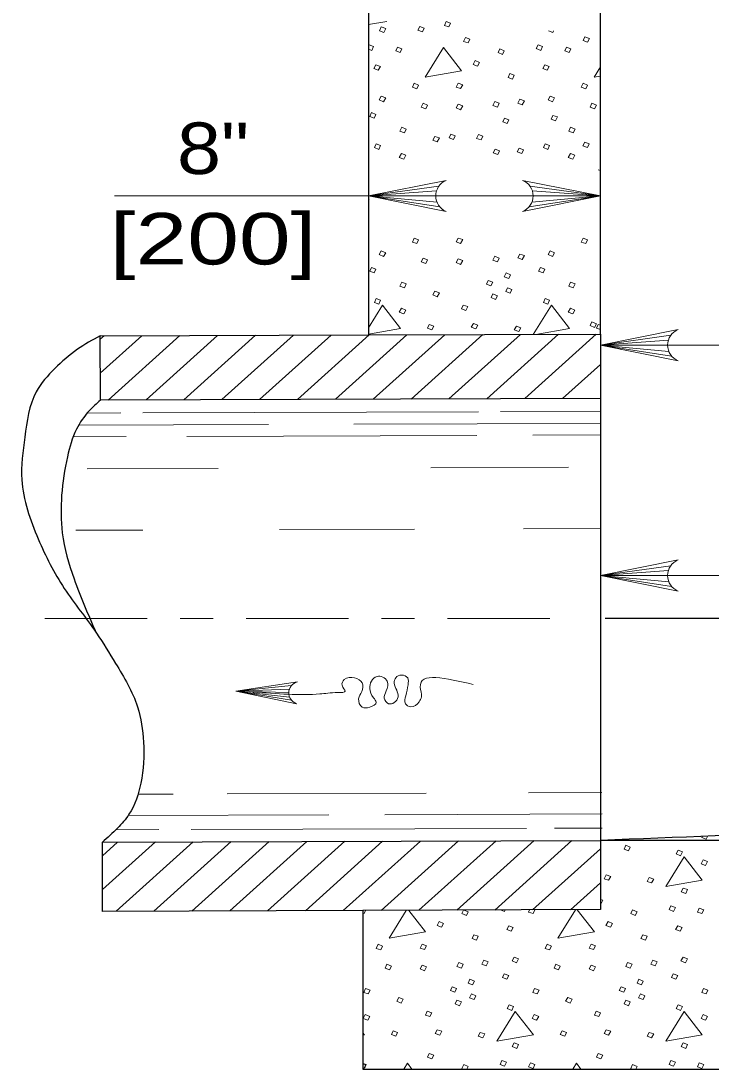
# Model space of a CAD drawing. Extents: x 1083.1 to 1123, y 697.4 to 741.4.
# Drawn here: x 1086.984 to 1089.075, y 699.494 to 702.669 of the extents above; entities that cross this region are included whole.
import ezdxf
from ezdxf.enums import TextEntityAlignment as Align

# ---------------------------------------------------------------- set-up
doc = ezdxf.new("R2010")
doc.units = 0
doc.header["$LTSCALE"] = 0.062
doc.linetypes.add('DOT_DASHED', pattern=[7.7, 5, -1.2, 0.3, -1.2])
doc.layers.add('1', color=7, linetype='Continuous', lineweight=13)

msp = doc.modelspace()

# ---------------------------------------------------------------- linework, layer by layer
at = {"layer": '1', "lineweight": 25}
for p, q in [((1088.03742, 703.9655), (1088.03742, 701.71783)), ((1088.74, 701.72025), (1088.74, 703.03767)), ((1088.74, 701.72025), (1088.74, 700.18692)), ((1095.16083, 700.18692), (1088.74, 700.18692))]:
    msp.add_line(p, q, dxfattribs=at)
at = {"layer": '1'}
for p, q in [((1088.03742, 702.65775), (1088.09258, 702.66742)), ((1088.03742, 702.59242), (1088.03933, 702.59642)), ((1088.73342, 702.21817), (1088.74, 702.21583)), ((1088.25067, 702.16858), (1088.03742, 702.13875)), ((1088.2435, 702.15383), (1088.03742, 702.13875)), ((1088.52675, 702.16858), (1088.74, 702.13875)), ((1088.53392, 702.15383), (1088.74, 702.13875)), ((1088.74, 702.13875), (1087.26767, 702.13875)), ((1088.24125, 702.13875), (1088.03742, 702.13875)), ((1088.24508, 702.11958), (1088.03742, 702.13875)), ((1088.25325, 702.10575), (1088.03742, 702.13875)), ((1088.03742, 702.12375), (1088.03933, 702.12767)), ((1088.52425, 702.10575), (1088.74, 702.13875)), ((1088.53242, 702.11958), (1088.74, 702.13875)), ((1088.53617, 702.13875), (1088.74, 702.13875)), ((1088.07975, 701.80767), (1088.03742, 701.73958)), ((1088.59158, 701.80767), (1088.53692, 701.7195)), ((1088.73342, 701.7495), (1088.74, 701.74717)), ((1087.2245, 701.70458), (1087.23633, 701.71508)), ((1087.225, 701.60208), (1087.351, 701.7155)), ((1087.24883, 701.52067), (1087.46575, 701.71592)), ((1087.36358, 701.521), (1087.5805, 701.71625)), ((1087.47825, 701.52142), (1087.69517, 701.71667)), ((1087.593, 701.52183), (1087.80992, 701.717)), ((1087.70767, 701.52217), (1087.92467, 701.71742)), ((1087.82242, 701.52258), (1088.03942, 701.71783)), ((1087.93717, 701.523), (1088.15417, 701.71825)), ((1088.05192, 701.52342), (1088.26883, 701.71858)), ((1088.16667, 701.52375), (1088.38358, 701.719)), ((1088.28142, 701.52417), (1088.49833, 701.71942)), ((1088.39608, 701.5245), (1088.613, 701.71983)), ((1088.51083, 701.52492), (1088.72783, 701.72017)), ((1088.541, 701.71958), (1088.54108, 701.71958)), ((1088.54108, 701.71958), (1088.54117, 701.71958)), ((1088.54117, 701.71958), (1088.54125, 701.71958)), ((1088.54125, 701.71958), (1088.54142, 701.71958)), ((1088.54142, 701.71958), (1088.54158, 701.71958)), ((1088.54158, 701.71958), (1088.54175, 701.71958)), ((1088.54175, 701.71958), (1088.54192, 701.71958)), ((1088.54192, 701.71958), (1088.54208, 701.71958)), ((1088.54208, 701.71958), (1088.54225, 701.71958)), ((1088.54225, 701.71958), (1088.54242, 701.71958)), ((1088.54242, 701.71958), (1088.54267, 701.71958)), ((1088.54267, 701.71958), (1088.54283, 701.71958)), ((1088.54283, 701.71958), (1088.543, 701.71958)), ((1088.543, 701.71958), (1088.54317, 701.71958)), ((1088.54317, 701.71958), (1088.54333, 701.71958)), ((1088.54333, 701.71958), (1088.5435, 701.71958)), ((1088.5435, 701.71958), (1088.54375, 701.71958)), ((1088.54375, 701.71958), (1088.54392, 701.71958)), ((1088.54392, 701.71958), (1088.54408, 701.71958)), ((1088.54408, 701.71958), (1088.54425, 701.71958)), ((1088.54425, 701.71958), (1088.54442, 701.71958)), ((1088.54442, 701.71958), (1088.54458, 701.71958)), ((1088.54458, 701.71958), (1088.54483, 701.71958)), ((1088.54483, 701.71958), (1088.545, 701.71958)), ((1088.95333, 701.71675), (1088.74, 701.68692)), ((1088.94608, 701.702), (1088.74, 701.68692)), ((1090.56375, 701.68692), (1088.74, 701.68692)), ((1088.94392, 701.68692), (1088.74, 701.68692)), ((1088.94767, 701.66775), (1088.74, 701.68692)), ((1088.95583, 701.65392), (1088.74, 701.68692)), ((1088.62558, 701.52533), (1088.74, 701.62833)), ((1087.28708, 701.48167), (1087.18492, 701.48133)), ((1088.37108, 701.48542), (1087.35375, 701.48192)), ((1088.74008, 701.48667), (1088.43775, 701.48567)), ((1087.73458, 701.4465), (1087.15925, 701.44458)), ((1088.74017, 701.45), (1087.993, 701.44742)), ((1087.30375, 701.41), (1087.14358, 701.40942)), ((1088.36542, 701.41367), (1087.48725, 701.41067)), ((1088.74042, 701.41492), (1088.53508, 701.41425)), ((1088.64342, 701.317), (1088.22642, 701.3155)), ((1087.58167, 701.31333), (1087.18558, 701.312)), ((1087.35367, 701.12683), (1087.15083, 701.12617)), ((1088.1765, 701.12967), (1087.76792, 701.12833)), ((1088.7415, 701.13158), (1088.50725, 701.13083)), ((1088.95333, 701.019), (1088.74, 700.98917)), ((1088.94608, 701.00425), (1088.74, 700.98917)), ((1094.45983, 700.98917), (1088.74, 700.98917)), ((1088.94392, 700.98917), (1088.74, 700.98917)), ((1088.94767, 700.97), (1088.74, 700.98917)), ((1088.95583, 700.95617), (1088.74, 700.98917)), ((1087.80417, 700.65567), (1087.63575, 700.63925)), ((1087.798, 700.64533), (1087.63575, 700.63925)), ((1087.796, 700.63475), (1087.63575, 700.63925)), ((1087.7985, 700.62108), (1087.63575, 700.63925)), ((1087.8045, 700.61117), (1087.63575, 700.63925)), ((1088.74492, 700.332), (1088.52233, 700.33117)), ((1087.44533, 700.32742), (1087.33933, 700.32717)), ((1088.21208, 700.33008), (1087.60958, 700.328)), ((1087.91692, 700.26408), (1087.30883, 700.262)), ((1088.74525, 700.26692), (1088.08725, 700.26467)), ((1087.40267, 700.21967), (1087.27175, 700.21917)), ((1088.51625, 700.22342), (1087.50008, 700.22)), ((1088.74542, 700.22425), (1088.60133, 700.22375)), ((1087.23125, 700.1405), (1087.27725, 700.18192)), ((1087.23167, 700.038), (1087.392, 700.18233)), ((1087.27267, 699.97217), (1087.50667, 700.18275)), ((1087.38742, 699.9725), (1087.6215, 700.18308)), ((1087.50225, 699.97283), (1087.73625, 700.18342)), ((1087.61692, 699.97325), (1087.85092, 700.18383)), ((1087.73167, 699.97367), (1087.96567, 700.18425)), ((1087.84633, 699.97408), (1088.08042, 700.18467)), ((1087.96108, 699.9745), (1088.19508, 700.18508)), ((1088.07583, 699.97475), (1088.30992, 700.1855)), ((1088.1905, 699.97517), (1088.42467, 700.18583)), ((1088.30533, 699.97558), (1088.53933, 700.18617)), ((1088.42008, 699.976), (1088.65408, 700.18658)), ((1088.53483, 699.97642), (1088.74, 700.16117)), ((1088.6495, 699.97683), (1088.74, 700.05825)), ((1088.15542, 699.51175), (1088.14467, 699.49442)), ((1088.16892, 699.49442), (1088.15542, 699.51175)), ((1088.66725, 699.51175), (1088.6565, 699.49442)), ((1088.68075, 699.49442), (1088.66725, 699.51175))]:
    msp.add_line(p, q, dxfattribs=at)
at = {"layer": '1', "linetype": 'DOT_DASHED'}
msp.add_line((1088.58675, 700.85858), (1086.9945, 700.85858), dxfattribs=at)
at = {"layer": '1'}
for points in [[(1088.07617, 702.65058), (1088.08958, 702.64567), (1088.08417, 702.63358), (1088.07075, 702.63925)], [(1088.19258, 702.65225), (1088.206, 702.64742), (1088.20067, 702.63608), (1088.18717, 702.64092)], [(1088.27283, 702.66683), (1088.28625, 702.662), (1088.28092, 702.65067), (1088.26742, 702.6555)], [(1088.33117, 702.61825), (1088.34458, 702.61333), (1088.33925, 702.60208), (1088.32575, 702.60692)], [(1088.6935, 702.62067), (1088.70692, 702.61583), (1088.70158, 702.6045), (1088.68808, 702.60933)], [(1088.1255, 702.58992), (1088.139, 702.58425), (1088.13358, 702.573), (1088.12008, 702.57783)], [(1088.26467, 702.58833), (1088.209, 702.49858), (1088.3195, 702.518)], [(1088.55117, 702.59642), (1088.56467, 702.59158), (1088.55925, 702.57942), (1088.54575, 702.58508)], [(1088.63742, 702.58992), (1088.65083, 702.58425), (1088.64542, 702.573), (1088.632, 702.57783)], [(1088.43533, 702.58425), (1088.44883, 702.57858), (1088.44342, 702.56733), (1088.42992, 702.573)], [(1088.06, 702.53583), (1088.07342, 702.53092), (1088.06717, 702.51967), (1088.05367, 702.5245)], [(1088.36075, 702.54875), (1088.37425, 702.54308), (1088.368, 702.53175), (1088.3545, 702.53658)], [(1088.57183, 702.53583), (1088.58533, 702.53092), (1088.579, 702.51967), (1088.5655, 702.5245)], [(1088.46583, 702.50917), (1088.47933, 702.50425), (1088.47392, 702.49217), (1088.4605, 702.49783)], [(1088.17583, 702.48), (1088.18925, 702.47442), (1088.18392, 702.46308), (1088.17042, 702.46792)], [(1088.30958, 702.48), (1088.32308, 702.47517), (1088.31675, 702.46383), (1088.30333, 702.46875)], [(1088.68767, 702.48), (1088.70117, 702.47442), (1088.69575, 702.46308), (1088.68225, 702.46792)], [(1088.07617, 702.44125), (1088.08958, 702.43558), (1088.08333, 702.42425), (1088.06983, 702.42992)], [(1088.49642, 702.43158), (1088.50983, 702.42667), (1088.50358, 702.41458), (1088.49008, 702.42025)], [(1088.588, 702.44125), (1088.60142, 702.43558), (1088.59517, 702.42425), (1088.58167, 702.42992)], [(1088.20275, 702.41942), (1088.21617, 702.41375), (1088.21083, 702.40242), (1088.19733, 702.40808)], [(1088.30958, 702.417), (1088.32308, 702.41217), (1088.31675, 702.4), (1088.30333, 702.40567)], [(1088.42008, 702.42508), (1088.4335, 702.41942), (1088.42817, 702.40808), (1088.41467, 702.413)], [(1088.71458, 702.41942), (1088.72808, 702.41375), (1088.72267, 702.40242), (1088.70925, 702.40808)], [(1088.0465, 702.39117), (1088.06, 702.3855), (1088.05458, 702.37417), (1088.04108, 702.37983)], [(1088.44958, 702.37433), (1088.463, 702.3695), (1088.45767, 702.35817), (1088.44417, 702.363)], [(1088.59633, 702.38283), (1088.60983, 702.378), (1088.60442, 702.36667), (1088.59092, 702.3715)], [(1088.13808, 702.34667), (1088.15158, 702.341), (1088.14617, 702.32975), (1088.13267, 702.33458)], [(1088.64992, 702.34667), (1088.66342, 702.341), (1088.658, 702.32975), (1088.64458, 702.33458)], [(1088.23867, 702.31925), (1088.25217, 702.31433), (1088.24583, 702.30225), (1088.23242, 702.30792)], [(1088.28692, 702.32592), (1088.30042, 702.32108), (1088.295, 702.30975), (1088.28158, 702.31467)], [(1088.37058, 702.3245), (1088.38408, 702.31967), (1088.37867, 702.30833), (1088.36525, 702.31325)], [(1088.69267, 702.30175), (1088.70608, 702.29692), (1088.70075, 702.28558), (1088.68725, 702.29042)], [(1088.06083, 702.29658), (1088.07433, 702.29175), (1088.06892, 702.27967), (1088.0555, 702.28525)], [(1088.13717, 702.2675), (1088.15067, 702.26183), (1088.14433, 702.2505), (1088.13092, 702.25533)], [(1088.42117, 702.28042), (1088.43458, 702.27558), (1088.42925, 702.26425), (1088.41575, 702.26908)], [(1088.49375, 702.28325), (1088.50725, 702.27842), (1088.50183, 702.26708), (1088.48833, 702.27192)], [(1088.57275, 702.29658), (1088.58617, 702.29175), (1088.58083, 702.27967), (1088.56733, 702.28525)], [(1088.64908, 702.2675), (1088.6625, 702.26183), (1088.65625, 702.2505), (1088.64275, 702.25533)], [(1088.17583, 702.01133), (1088.18925, 702.00567), (1088.18392, 701.99433), (1088.17042, 701.99917)], [(1088.30958, 702.01133), (1088.32308, 702.0065), (1088.31675, 701.99517), (1088.30333, 702)], [(1088.68767, 702.01133), (1088.70117, 702.00567), (1088.69575, 701.99433), (1088.68225, 701.99917)], [(1088.07617, 701.9725), (1088.08958, 701.96683), (1088.08333, 701.95558), (1088.06983, 701.96125)], [(1088.20275, 701.95075), (1088.21617, 701.94508), (1088.21083, 701.93375), (1088.19733, 701.93942)], [(1088.42008, 701.95642), (1088.4335, 701.95075), (1088.42817, 701.93942), (1088.41467, 701.94425)], [(1088.49642, 701.96283), (1088.50983, 701.958), (1088.50358, 701.94583), (1088.49008, 701.9515)], [(1088.588, 701.9725), (1088.60142, 701.96683), (1088.59517, 701.95558), (1088.58167, 701.96125)], [(1088.0465, 701.92242), (1088.06, 701.91675), (1088.05458, 701.9055), (1088.04108, 701.91108)], [(1088.30958, 701.94825), (1088.32308, 701.94342), (1088.31675, 701.93133), (1088.30333, 701.937)], [(1088.55833, 701.92242), (1088.57183, 701.91675), (1088.56642, 701.9055), (1088.553, 701.91108)], [(1088.45417, 701.9055), (1088.46767, 701.89983), (1088.46225, 701.8885), (1088.44883, 701.89333)], [(1088.13808, 701.878), (1088.15158, 701.87233), (1088.14617, 701.861), (1088.13267, 701.86583)], [(1088.40033, 701.88283), (1088.41375, 701.878), (1088.40842, 701.86667), (1088.39492, 701.8715)], [(1088.45867, 701.861), (1088.47217, 701.85533), (1088.46675, 701.84408), (1088.45325, 701.84967)], [(1088.64992, 701.878), (1088.66342, 701.87233), (1088.658, 701.861), (1088.64458, 701.86583)], [(1088.06083, 701.82792), (1088.07433, 701.823), (1088.06892, 701.81092), (1088.0555, 701.81658)], [(1088.23867, 701.8505), (1088.25217, 701.84567), (1088.24583, 701.8335), (1088.23242, 701.83917)], [(1088.41467, 701.84242), (1088.42817, 701.83675), (1088.42275, 701.8255), (1088.40925, 701.83108)], [(1088.57275, 701.82792), (1088.58617, 701.823), (1088.58083, 701.81092), (1088.56733, 701.81658)], [(1088.13717, 701.79883), (1088.15067, 701.79317), (1088.14433, 701.78183), (1088.13092, 701.78667)], [(1088.32483, 701.8085), (1088.33833, 701.80367), (1088.33292, 701.79233), (1088.3195, 701.79717)], [(1088.64908, 701.79883), (1088.6625, 701.79317), (1088.65625, 701.78183), (1088.64275, 701.78667)], [(1088.22158, 701.7495), (1088.23508, 701.74467), (1088.22967, 701.73333), (1088.21617, 701.73817)], [(1088.35542, 701.75275), (1088.36883, 701.74792), (1088.36258, 701.73658), (1088.34908, 701.74142)], [(1088.48558, 701.74467), (1088.49908, 701.73983), (1088.49283, 701.7285), (1088.47933, 701.73333)], [(1088.71458, 701.75742), (1088.72808, 701.75175), (1088.72267, 701.74042), (1088.70925, 701.74608)], [(1088.81725, 700.172), (1088.83075, 700.16633), (1088.82533, 700.155), (1088.81183, 700.16067)], [(1088.97533, 700.15742), (1088.98875, 700.15258), (1088.98333, 700.14042), (1088.96992, 700.14608)], [(1088.99417, 700.13725), (1088.9385, 700.0475), (1089.04892, 700.06692)], [(1089.05158, 700.12833), (1089.06508, 700.12267), (1089.05883, 700.11133), (1089.04533, 700.11625)], [(1088.758, 700.08225), (1088.77142, 700.07742), (1088.76517, 700.06608), (1088.75167, 700.07092)], [(1088.88817, 700.07417), (1088.90167, 700.06933), (1088.89533, 700.058), (1088.88192, 700.06283)], [(1088.99058, 700.04267), (1089.004, 700.03783), (1088.99867, 700.02567), (1088.98517, 700.03133)], [(1088.95375, 699.9885), (1088.96725, 699.98367), (1088.96183, 699.97158), (1088.94833, 699.97725)], [(1089.03992, 699.98208), (1089.05342, 699.97642), (1089.048, 699.96508), (1089.03458, 699.96992)], [(1088.83792, 699.97642), (1088.85133, 699.97075), (1088.846, 699.95942), (1088.8325, 699.96508)], [(1088.2515, 699.94083), (1088.265, 699.93517), (1088.25867, 699.92383), (1088.24525, 699.92875)], [(1088.4625, 699.92792), (1088.476, 699.92308), (1088.46975, 699.91175), (1088.45625, 699.91658)], [(1088.76333, 699.94083), (1088.77683, 699.93517), (1088.77058, 699.92383), (1088.75708, 699.92875)], [(1088.97442, 699.92792), (1088.98783, 699.92308), (1088.98158, 699.91175), (1088.96808, 699.91658)], [(1088.35658, 699.90125), (1088.37, 699.89642), (1088.36467, 699.88425), (1088.35117, 699.88992)], [(1088.86842, 699.90125), (1088.88192, 699.89642), (1088.8765, 699.88425), (1088.86308, 699.88992)], [(1088.0665, 699.87217), (1088.08, 699.8665), (1088.07458, 699.85517), (1088.06108, 699.86)], [(1088.20033, 699.87217), (1088.21375, 699.86733), (1088.2075, 699.856), (1088.194, 699.86083)], [(1088.57842, 699.87217), (1088.59183, 699.8665), (1088.58642, 699.85517), (1088.573, 699.86)], [(1088.71217, 699.87217), (1088.72567, 699.86733), (1088.71933, 699.856), (1088.70592, 699.86083)], [(1088.38708, 699.82367), (1088.40058, 699.81883), (1088.39425, 699.80667), (1088.38083, 699.81233)], [(1088.47867, 699.83342), (1088.49217, 699.82775), (1088.48592, 699.81642), (1088.47242, 699.82208)], [(1088.899, 699.82367), (1088.91242, 699.81883), (1088.90617, 699.80667), (1088.89267, 699.81233)], [(1088.99058, 699.83342), (1089.004, 699.82775), (1088.99775, 699.81642), (1088.98425, 699.82208)], [(1088.09342, 699.81158), (1088.10692, 699.80592), (1088.10158, 699.79458), (1088.08808, 699.80025)], [(1088.20033, 699.80908), (1088.21375, 699.80425), (1088.2075, 699.79217), (1088.194, 699.79783)], [(1088.31075, 699.81725), (1088.32425, 699.81158), (1088.31883, 699.80025), (1088.30542, 699.80508)], [(1088.60533, 699.81158), (1088.61875, 699.80592), (1088.61342, 699.79458), (1088.59992, 699.80025)], [(1088.71217, 699.80908), (1088.72567, 699.80425), (1088.71933, 699.79217), (1088.70592, 699.79783)], [(1088.82267, 699.81725), (1088.83608, 699.81158), (1088.83075, 699.80025), (1088.81725, 699.80508)], [(1088.34492, 699.76625), (1088.35833, 699.76067), (1088.353, 699.74933), (1088.3395, 699.75417)], [(1088.44908, 699.78325), (1088.4625, 699.77758), (1088.45717, 699.76625), (1088.44367, 699.77192)], [(1088.85675, 699.76625), (1088.87025, 699.76067), (1088.86483, 699.74933), (1088.85133, 699.75417)], [(1088.96092, 699.78325), (1088.97442, 699.77758), (1088.969, 699.76625), (1088.9555, 699.77192)], [(1088.02883, 699.73883), (1088.04225, 699.73317), (1088.03692, 699.72183), (1088.02342, 699.72667)], [(1088.291, 699.74367), (1088.3045, 699.73883), (1088.29908, 699.7275), (1088.28567, 699.73233)], [(1088.54067, 699.73883), (1088.55417, 699.73317), (1088.54875, 699.72183), (1088.53525, 699.72667)], [(1088.80292, 699.74367), (1088.81633, 699.73883), (1088.811, 699.7275), (1088.7975, 699.73233)], [(1089.0525, 699.73883), (1089.066, 699.73317), (1089.06058, 699.72183), (1089.04717, 699.72667)], [(1088.12942, 699.71133), (1088.14283, 699.7065), (1088.13658, 699.69433), (1088.12308, 699.7)], [(1088.30542, 699.70325), (1088.31883, 699.69758), (1088.3135, 699.68625), (1088.3, 699.69192)], [(1088.34942, 699.72183), (1088.36283, 699.71617), (1088.3575, 699.70492), (1088.344, 699.7105)], [(1088.64125, 699.71133), (1088.65467, 699.7065), (1088.64842, 699.69433), (1088.63492, 699.7)], [(1088.81725, 699.70325), (1088.83075, 699.69758), (1088.82533, 699.68625), (1088.81183, 699.69192)], [(1088.86125, 699.72183), (1088.87475, 699.71617), (1088.86933, 699.70492), (1088.85583, 699.7105)], [(1088.21558, 699.66933), (1088.22908, 699.6645), (1088.22367, 699.65317), (1088.21017, 699.658)], [(1088.48233, 699.6685), (1088.42658, 699.57883), (1088.53708, 699.59825)], [(1088.46342, 699.68875), (1088.47692, 699.68383), (1088.4715, 699.67175), (1088.458, 699.67742)], [(1088.72742, 699.66933), (1088.74092, 699.6645), (1088.7355, 699.65317), (1088.72208, 699.658)], [(1088.99417, 699.6685), (1088.9385, 699.57883), (1089.04892, 699.59825)], [(1088.97533, 699.68875), (1088.98875, 699.68383), (1088.98333, 699.67175), (1088.96992, 699.67742)], [(1088.02792, 699.65967), (1088.04133, 699.654), (1088.03508, 699.64267), (1088.02158, 699.6475)], [(1088.53975, 699.65967), (1088.55325, 699.654), (1088.54692, 699.64267), (1088.5335, 699.6475)], [(1089.05158, 699.65967), (1089.06508, 699.654), (1089.05883, 699.64267), (1089.04533, 699.6475)], [(1088.11233, 699.61033), (1088.12575, 699.6055), (1088.12042, 699.59417), (1088.10692, 699.599)], [(1088.24608, 699.61358), (1088.25958, 699.60875), (1088.25333, 699.59742), (1088.23983, 699.60225)], [(1088.37633, 699.6055), (1088.38983, 699.60067), (1088.3835, 699.58933), (1088.37, 699.59417)], [(1088.62417, 699.61033), (1088.63767, 699.6055), (1088.63225, 699.59417), (1088.61875, 699.599)], [(1088.758, 699.61358), (1088.77142, 699.60875), (1088.76517, 699.59742), (1088.75167, 699.60225)], [(1088.88817, 699.6055), (1088.90167, 699.60067), (1088.89533, 699.58933), (1088.88192, 699.59417)], [(1088.47867, 699.574), (1088.49217, 699.56908), (1088.48675, 699.557), (1088.47333, 699.56267)], [(1088.99058, 699.574), (1089.004, 699.56908), (1088.99867, 699.557), (1088.98517, 699.56267)], [(1088.22183, 699.54167), (1088.23533, 699.53675), (1088.22992, 699.5255), (1088.2165, 699.53033)], [(1088.73375, 699.54167), (1088.74717, 699.53675), (1088.74183, 699.5255), (1088.72833, 699.53033)], [(1088.44192, 699.51983), (1088.45533, 699.515), (1088.44992, 699.50283), (1088.4365, 699.5085)], [(1088.52808, 699.51333), (1088.54158, 699.50767), (1088.53617, 699.49642), (1088.52267, 699.50125)], [(1088.95375, 699.51983), (1088.96725, 699.515), (1088.96183, 699.50283), (1088.94833, 699.5085)], [(1089.03992, 699.51333), (1089.05342, 699.50767), (1089.048, 699.49642), (1089.03458, 699.50125)]]:
    msp.add_lwpolyline(points, close=True, dxfattribs=at)
for points in [[(1088.5985, 702.639), (1088.59608, 702.63358), (1088.58308, 702.639)], [(1088.03933, 702.59642), (1088.05275, 702.59158), (1088.04742, 702.57942), (1088.03742, 702.58367)], [(1088.74, 702.52942), (1088.72092, 702.49858), (1088.74, 702.502)], [(1088.273, 702.09167), (1088.03742, 702.13875), (1088.273, 702.18592)], [(1088.50442, 702.09167), (1088.74, 702.13875), (1088.50442, 702.18592)], [(1088.03742, 701.72033), (1088.1345, 701.73733), (1088.07975, 701.80767)], [(1088.545, 701.71958), (1088.64633, 701.73733), (1088.59158, 701.80767)], [(1088.74, 701.73392), (1088.72808, 701.73817), (1088.73342, 701.7495)], [(1088.97558, 701.63975), (1088.74, 701.68692), (1088.97558, 701.734)], [(1088.97558, 700.942), (1088.74, 700.98917), (1088.97558, 701.03625)], [(1087.81975, 700.60067), (1087.63575, 700.63925), (1087.822, 700.66742)], [(1089.06467, 700.19908), (1089.06058, 700.19058), (1089.04717, 700.19542), (1089.0485, 700.1985)], [(1088.74017, 700.13342), (1088.74092, 700.13317), (1088.74017, 700.13175)], [(1088.74075, 700.00783), (1088.74717, 700.0055), (1088.74183, 699.99417), (1088.74075, 699.99458)], [(1088.02892, 699.97467), (1088.02433, 699.96508), (1088.02083, 699.96642)], [(1088.15208, 699.97508), (1088.09975, 699.89075), (1088.21017, 699.91017), (1088.15958, 699.97508)], [(1088.32775, 699.97567), (1088.3395, 699.97075), (1088.33417, 699.95942), (1088.32067, 699.96508), (1088.32567, 699.97567)], [(1088.452, 699.97617), (1088.44992, 699.97158), (1088.43917, 699.97608)], [(1088.5415, 699.97642), (1088.54158, 699.97642), (1088.53617, 699.96508), (1088.52267, 699.96992), (1088.52558, 699.97642)], [(1088.665, 699.97692), (1088.61158, 699.89075), (1088.72208, 699.91017), (1088.67008, 699.97692)], [(1088.02083, 699.59742), (1088.02525, 699.59825), (1088.02083, 699.60383)], [(1088.32525, 699.49442), (1088.32067, 699.49642), (1088.326, 699.50767)], [(1088.326, 699.50767), (1088.3395, 699.50208), (1088.33592, 699.49442)], [(1088.83708, 699.49442), (1088.8325, 699.49642), (1088.83792, 699.50767)], [(1088.83792, 699.50767), (1088.85133, 699.50208), (1088.84775, 699.49442)]]:
    msp.add_lwpolyline(points, dxfattribs=at)
at = {"layer": '1', "lineweight": 25}
for points in [[(1087.2245, 701.71508), (1088.03742, 701.71783), (1088.74, 701.72025)], [(1088.74, 701.52575), (1087.22533, 701.52058), (1087.2245, 701.71508)], [(1094.45983, 700.85858), (1092.14192, 700.85858), (1088.75442, 700.85858)], [(1087.23108, 700.18175), (1088.74, 700.18692), (1088.74, 699.97717)], [(1088.74083, 699.97717), (1088.02083, 699.97467), (1087.23192, 699.972), (1087.23108, 700.18175)], [(1088.02083, 699.97467), (1088.02083, 699.49442), (1095.16083, 699.49442)], [(1088.02083, 699.51142), (1088.02967, 699.50767), (1088.02433, 699.49642), (1088.02083, 699.49767)]]:
    msp.add_lwpolyline(points, dxfattribs=at)
at = {"layer": '1'}
for centre, start, end in [((1088.29203, 702.13882), 112.08782, 247.91395), ((1088.4854, 702.13882), 292.08605, 67.91218), ((1088.99463, 701.68694), 112.08782, 247.91395), ((1088.99463, 700.98921), 112.08782, 247.91395)]:
    msp.add_arc(centre, 0.05085, start, end, dxfattribs=at)
msp.add_ellipse((1087.83591, 700.63361), major_axis=(-0.03997, 0), ratio=0.899905, start_param=5.0665441, end_param=7.4371572, dxfattribs=at)
at = {"layer": '1', "lineweight": 25}
for points in [[(1087.2245, 701.71508), (1087.15542, 701.67433), (1087.087, 701.61592), (1087.031, 701.54583), (1086.99617, 701.40858), (1086.98708, 701.27925), (1087.03675, 701.09983), (1087.11583, 700.95017), (1087.21333, 700.81492), (1087.27117, 700.72308), (1087.33775, 700.5915), (1087.35583, 700.48467), (1087.34792, 700.3605), (1087.31183, 700.26608), (1087.27683, 700.22383), (1087.23108, 700.18175)], [(1087.22533, 701.52058), (1087.19092, 701.48783), (1087.1525, 701.43208), (1087.12517, 701.349), (1087.10783, 701.23233), (1087.10967, 701.11842), (1087.14525, 700.979), (1087.2115, 700.81767)], [(1093.41108, 700.37683), (1093.14842, 700.34575), (1092.39425, 700.30808), (1091.48667, 700.28242), (1090.13167, 700.23908), (1088.74, 700.18692)]]:
    msp.add_spline(points, degree=3, dxfattribs=at)
at = {"layer": '1'}
msp.add_spline([(1088.35475, 700.659), (1088.1945, 700.65092), (1088.19767, 700.62167), (1088.19117, 700.60708), (1088.1655, 700.59142), (1088.1495, 700.60092), (1088.15067, 700.62492), (1088.15725, 700.65825), (1088.15625, 700.67925), (1088.13817, 700.68758), (1088.12, 700.67933), (1088.11558, 700.66358), (1088.12292, 700.64167), (1088.12717, 700.62183), (1088.11533, 700.60408), (1088.09825, 700.601), (1088.0855, 700.61775), (1088.091, 700.63958), (1088.09433, 700.66883), (1088.0805, 700.68142), (1088.06342, 700.68358), (1088.04625, 700.66892), (1088.04183, 700.64708), (1088.05242, 700.61875), (1088.06092, 700.60517), (1088.04158, 700.59067), (1088.01817, 700.59067), (1088.00758, 700.61575), (1088.01725, 700.63767), (1088.01842, 700.66375), (1087.99508, 700.67942), (1087.96408, 700.67425), (1087.9575, 700.65658), (1087.96708, 700.63883), (1087.94567, 700.63467), (1087.89017, 700.63058), (1087.68692, 700.63633)], degree=3, dxfattribs=at)

# ---------------------------------------------------------------- texts
for s, width, p in [('8"', 1.15, (1087.56658, 702.20525)), ('[200]', 1.35, (1087.56658, 701.93125))]:
    msp.add_text(s, height=0.156, dxfattribs=dict(at, width=width)).set_placement(p, align=Align.CENTER)

doc.saveas('drawing.dxf')
